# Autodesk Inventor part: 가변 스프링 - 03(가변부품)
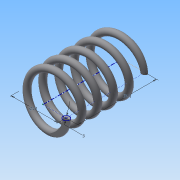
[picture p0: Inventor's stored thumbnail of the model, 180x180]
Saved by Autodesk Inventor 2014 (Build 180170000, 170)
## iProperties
Created: 2015-09
Part Number: 가변 스프링 - 03(가변부품)
Material: 강철, 탄소
Document SubType Name: Modeling
Designer: study
Density: 7.87 g/cm^3
Appearance: 반연마
Mass: 18.7571 g
Surface Area: 32.4302 cm^2
Volume: 2.38337 cm^3
Author: study
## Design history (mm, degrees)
sketch "스케치1"
  geometry: L1 (0, 26.195)-(11, 26.195); L2 (11, 26.195)-(11, 0); L3 (11, 0)-(0, 0); L4 (0, 0)-(0, 26.195); C1 r 1.5 at (11, 0); 1 further point
  constraints: 8 end point, 2 coincident, 2 parallel, 1 centre point, 1 horizontal, 1 perpendicular
  dimensions: "d0" = 3 diameter of C1; "d1" = 22 diameter of L2 L4; "d2" = 26.1955 distance of L1.end L2.end (derived)
feature "코일1" sketch "스케치1" pitch "d3" = 10; turns "d5" = 5; dims "d4" = 26.1955 (= d2), "d6" = 0, angle "d7" = 90 deg, angle "d8" = 90 deg, "d9" = 0, "d10" = 0
sketch "스케치2"
  geometry: L1 (-12.5, 0)-(-9.5, 0) reference; 1 further point
  constraints: 1 horizontal alignment
extrude "돌출1" cut sketch "스케치2" stored distance "d11" = 10; taper "d12" = 0 deg
node "작업 평면1"
sketch "스케치3"
  geometry: L1 (-9.5, 0)-(-12.5, 0) reference; 1 further point
  constraints: 1 horizontal alignment
extrude "돌출2" cut sketch "스케치3" stored distance "d14" = 10; taper "d15" = 0 deg
node "솔리드1"
node "절단 모서리 투영1"
node "절단 모서리 투영2"
other parameters: "d13" = 26.1955 (= d2)
